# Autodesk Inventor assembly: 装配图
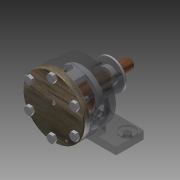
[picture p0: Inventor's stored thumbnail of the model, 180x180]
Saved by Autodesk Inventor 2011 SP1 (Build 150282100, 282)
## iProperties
Created: 2014-03
Part Number: 装配图
Document SubType Name: Assembly
Designer: Administrator
Author: Administrator
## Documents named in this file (14)
- C:\Users\Administrator\Desktop\三元子泵\装配图.iam
- C:\Users\Administrator\Desktop\三元子泵\泵体.ipt
- C:\Users\Administrator\Desktop\三元子泵\泵盖.ipt
- C:\Users\Administrator\Desktop\三元子泵\衬套.ipt
- C:\Users\Administrator\Desktop\三元子泵\大滑块.ipt
- C:\Users\Administrator\Desktop\三元子泵\垫片.ipt
- C:\Users\Administrator\Desktop\三元子泵\螺钉M4×8.ipt
- C:\Users\Administrator\Desktop\三元子泵\螺钉M6×16.ipt
- C:\Users\Administrator\Desktop\三元子泵\密封环.ipt
- C:\Users\Administrator\Desktop\三元子泵\销钉3m6×14.ipt
- C:\Users\Administrator\Desktop\三元子泵\小滑块.ipt
- C:\Users\Administrator\Desktop\三元子泵\小轴.ipt
- C:\Users\Administrator\Desktop\三元子泵\压盖.ipt
- C:\Users\Administrator\Desktop\三元子泵\转子轴.ipt
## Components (20 placed, 13 different names)
1. 泵体:1 — 插入:1, 配合:1, 配合:2, 配合:14, 配合:15, 表面齐平:1, 配合:25, 配合:26, 配合:27, 配合:30
2. 泵盖:1 — 配合:28, 配合:29, 配合:30, 配合:31, 表面齐平:2, 配合:32, 配合:33, 配合:34, 配合:35, 配合:36, 配合:37, 配合:38, 配合:39, 配合:40, 配合:41, 配合:42, 配合:43
3. 衬套:1 — 配合:2, 配合:6, 配合:7, 配合:10
4. 大滑块:1 — 配合:3, 配合:4, 配合:5, 配合:8, 配合:9, 配合:10, 配合:12
5. 垫片:1 — 配合:25, 配合:26, 配合:27, 配合:28, 配合:29
6. 螺钉M4×8:1 — 配合:17, 配合:18, 配合:19, 配合:20
7. 螺钉M6×16:1 — 配合:32, 配合:34
8. 密封环:1 — 表面齐平:1
9. 销钉3m6×14:1 — 配合:31, 表面齐平:2
10. 小滑块:1 — 配合:8, 配合:9, 配合:11, 配合:13
11. 小轴:1 — 配合:12, 配合:13
12. 压盖:1 — 配合:14, 配合:15, 配合:16, 配合:17, 配合:18, 配合:19, 配合:20, 配合:21, 配合:22, 配合:23, 配合:24
13. 转子轴:1 — 插入:1, 配合:1, 配合:3, 配合:4, 配合:5, 配合:6, 配合:7, 配合:11, 配合:16
14. 螺钉M4×8:2 — 配合:23, 配合:24
15. 螺钉M4×8:3 — 配合:21, 配合:22
16. 螺钉M6×16:2 — 配合:37, 配合:42
17. 螺钉M6×16:3 — 配合:33, 配合:35
18. 螺钉M6×16:4 — 配合:39, 配合:41
19. 螺钉M6×16:5 — 配合:36, 配合:43
20. 螺钉M6×16:6 — 配合:38, 配合:40
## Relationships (46: Mate 43, Flush 2, Insert 1)
- 插入:1 [Insert]: 泵体:1 ↔ 转子轴:1
- 配合:1 [Mate]: 泵体:1 ↔ 转子轴:1
- 配合:2 [Mate]: 泵体:1 ↔ 衬套:1
- 配合:3 [Mate]: 大滑块:1 ↔ 转子轴:1
- 配合:4 [Mate]: 大滑块:1 ↔ 转子轴:1
- 配合:5 [Mate]: 大滑块:1 ↔ 转子轴:1
- 配合:6 [Mate]: 衬套:1 ↔ 转子轴:1
- 配合:7 [Mate]: 衬套:1 ↔ 转子轴:1
- 配合:8 [Mate]: 大滑块:1 ↔ 小滑块:1
- 配合:9 [Mate]: 大滑块:1 ↔ 小滑块:1
- 配合:10 [Mate]: 衬套:1 ↔ 大滑块:1
- 配合:11 [Mate]: 小滑块:1 ↔ 转子轴:1
- 配合:12 [Mate]: 大滑块:1 ↔ 小轴:1
- 配合:13 [Mate]: 小滑块:1 ↔ 小轴:1
- 配合:14 [Mate]: 泵体:1 ↔ 压盖:1
- 配合:15 [Mate]: 泵体:1 ↔ 压盖:1
- 配合:16 [Mate]: 压盖:1 ↔ 转子轴:1
- 表面齐平:1 [Flush]: 泵体:1 ↔ 密封环:1
- 配合:17 [Mate]: 螺钉M4×8:1 ↔ 压盖:1
- 配合:18 [Mate]: 螺钉M4×8:1 ↔ 压盖:1
- 配合:19 [Mate]: 螺钉M4×8:1 ↔ 压盖:1
- 配合:20 [Mate]: 螺钉M4×8:1 ↔ 压盖:1
- 配合:21 [Mate]: 压盖:1 ↔ 螺钉M4×8:3
- 配合:22 [Mate]: 压盖:1 ↔ 螺钉M4×8:3
- 配合:23 [Mate]: 压盖:1 ↔ 螺钉M4×8:2
- 配合:24 [Mate]: 压盖:1 ↔ 螺钉M4×8:2
- 配合:25 [Mate]: 泵体:1 ↔ 垫片:1
- 配合:26 [Mate]: 泵体:1 ↔ 垫片:1
- 配合:27 [Mate]: 泵体:1 ↔ 垫片:1
- 配合:28 [Mate]: 泵盖:1 ↔ 垫片:1
- 配合:29 [Mate]: 泵盖:1 ↔ 垫片:1
- 配合:30 [Mate]: 泵体:1 ↔ 泵盖:1
- 配合:31 [Mate]: 泵盖:1 ↔ 销钉3m6×14:1
- 表面齐平:2 [Flush]: 泵盖:1 ↔ 销钉3m6×14:1
- 配合:32 [Mate]: 泵盖:1 ↔ 螺钉M6×16:1
- 配合:33 [Mate]: 泵盖:1 ↔ 螺钉M6×16:3
- 配合:34 [Mate]: 泵盖:1 ↔ 螺钉M6×16:1
- 配合:35 [Mate]: 泵盖:1 ↔ 螺钉M6×16:3
- 配合:36 [Mate]: 泵盖:1 ↔ 螺钉M6×16:5
- 配合:37 [Mate]: 泵盖:1 ↔ 螺钉M6×16:2
- 配合:38 [Mate]: 泵盖:1 ↔ 螺钉M6×16:6
- 配合:39 [Mate]: 泵盖:1 ↔ 螺钉M6×16:4
- 配合:40 [Mate]: 泵盖:1 ↔ 螺钉M6×16:6
- 配合:41 [Mate]: 泵盖:1 ↔ 螺钉M6×16:4
- 配合:42 [Mate]: 泵盖:1 ↔ 螺钉M6×16:2
- 配合:43 [Mate]: 泵盖:1 ↔ 螺钉M6×16:5
